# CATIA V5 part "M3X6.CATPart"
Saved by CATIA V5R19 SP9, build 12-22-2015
Part number: M3X6
Definition: design
Nomenclature: M3X6
Source: Unknown
Bounding box of the stored display mesh (mm): x -3.002 to 3.002, y -3.002 to 3.002, z 0 to 6
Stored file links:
  Z:\charly_robot\M3X6.CATPart
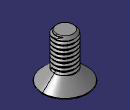
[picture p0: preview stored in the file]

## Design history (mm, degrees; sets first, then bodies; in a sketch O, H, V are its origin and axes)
AxisSystem1: origin (0, 0, 0), X (1, 0, 0), Y (0, 1, 0), Z (0, 0, 1)
Set1
  DatumSurface1 "OPEN_SHELL #245692"
Body1 (main body)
